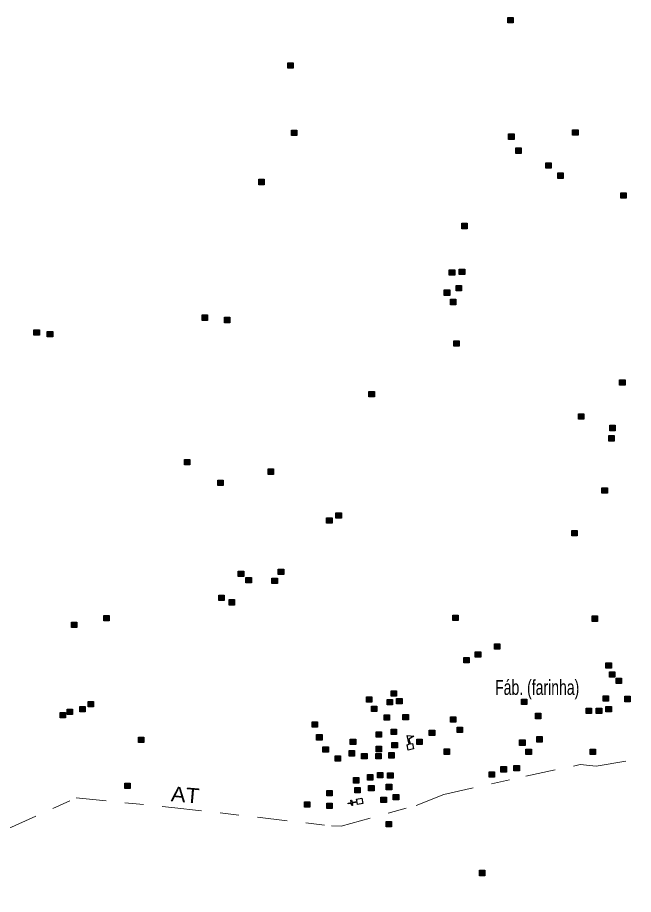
# Model space of a CAD drawing. Extents: x 220.8 to 246.7, y 7287.6 to 7315.8.
# Drawn here: x 236.618 to 239.906, y 7306.501 to 7311.184 of the extents above; entities that cross this region are included whole.
import ezdxf
from ezdxf.enums import TextEntityAlignment as Align

# ---------------------------------------------------------------- set-up
doc = ezdxf.new("R2010")
doc.units = 0
doc.header["$LTSCALE"] = 0.032
doc.linetypes.add('DOT_DASHED', pattern=[7.7, 5, -1.2, 0.3, -1.2])
for name, color, linetype, lineweight in [('2', 7, 'Continuous', 25), ('4', 7, 'Continuous', 25), ('56', 7, 'DOT_DASHED', 13), ('6', 7, 'Continuous', 25)]:
    doc.layers.add(name, color=color, linetype=linetype, lineweight=lineweight)
doc.layers.add('61', color=7, linetype='Continuous')

msp = doc.modelspace()

# ---------------------------------------------------------------- hatches: boundary and pattern name
at = {"layer": '2'}
for points in [[(239.235, 7311.1838), (239.264, 7311.1838), (239.264, 7311.1548), (239.235, 7311.1548)], [(238.0608, 7310.9416), (238.0898, 7310.9416), (238.0898, 7310.9126), (238.0608, 7310.9126)], [(238.0807, 7310.5831), (238.1097, 7310.5831), (238.1097, 7310.5541), (238.0807, 7310.5541)], [(239.2396, 7310.5621), (239.2686, 7310.5621), (239.2686, 7310.5331), (239.2396, 7310.5331)], [(239.5811, 7310.5847), (239.6101, 7310.5847), (239.6101, 7310.5557), (239.5811, 7310.5557)], [(239.278, 7310.4874), (239.307, 7310.4874), (239.307, 7310.4584), (239.278, 7310.4584)], [(239.4386, 7310.4083), (239.4676, 7310.4083), (239.4676, 7310.3793), (239.4386, 7310.3793)], [(237.9055, 7310.3202), (237.9345, 7310.3202), (237.9345, 7310.2912), (237.9055, 7310.2912)], [(239.5019, 7310.354), (239.5309, 7310.354), (239.5309, 7310.325), (239.5019, 7310.325)], [(239.8389, 7310.2477), (239.8679, 7310.2477), (239.8679, 7310.2187), (239.8389, 7310.2187)], [(238.9898, 7310.0849), (239.0188, 7310.0849), (239.0188, 7310.0559), (238.9898, 7310.0559)], [(238.9229, 7309.8363), (238.9519, 7309.8363), (238.9519, 7309.8073), (238.9229, 7309.8073)], [(238.9765, 7309.8397), (239.0055, 7309.8397), (239.0055, 7309.8107), (238.9765, 7309.8107)], [(238.8961, 7309.7292), (238.9251, 7309.7292), (238.9251, 7309.7002), (238.8961, 7309.7002)], [(238.9597, 7309.7526), (238.9887, 7309.7526), (238.9887, 7309.7236), (238.9597, 7309.7236)], [(238.9296, 7309.679), (238.9586, 7309.679), (238.9586, 7309.65), (238.9296, 7309.65)], [(237.6034, 7309.5957), (237.6324, 7309.5957), (237.6324, 7309.5667), (237.6034, 7309.5667)], [(237.7232, 7309.5828), (237.7522, 7309.5828), (237.7522, 7309.5538), (237.7232, 7309.5538)], [(236.7062, 7309.5166), (236.7352, 7309.5166), (236.7352, 7309.4876), (236.7062, 7309.4876)], [(236.777, 7309.5071), (236.806, 7309.5071), (236.806, 7309.4781), (236.777, 7309.4781)], [(238.9464, 7309.458), (238.9754, 7309.458), (238.9754, 7309.429), (238.9464, 7309.429)], [(239.8322, 7309.2493), (239.8612, 7309.2493), (239.8612, 7309.2203), (239.8322, 7309.2203)], [(238.4944, 7309.1868), (238.5234, 7309.1868), (238.5234, 7309.1578), (238.4944, 7309.1578)], [(239.6119, 7309.0679), (239.6409, 7309.0679), (239.6409, 7309.0389), (239.6119, 7309.0389)], [(239.7803, 7309.0063), (239.8093, 7309.0063), (239.8093, 7308.9773), (239.7803, 7308.9773)], [(239.7738, 7308.9512), (239.8028, 7308.9512), (239.8028, 7308.9222), (239.7738, 7308.9222)], [(237.5091, 7308.8237), (237.5381, 7308.8237), (237.5381, 7308.7947), (237.5091, 7308.7947)], [(237.9565, 7308.7731), (237.9855, 7308.7731), (237.9855, 7308.7441), (237.9565, 7308.7441)], [(237.6869, 7308.7132), (237.7159, 7308.7132), (237.7159, 7308.6842), (237.6869, 7308.6842)], [(239.7382, 7308.6726), (239.7672, 7308.6726), (239.7672, 7308.6436), (239.7382, 7308.6436)], [(238.2682, 7308.5123), (238.2972, 7308.5123), (238.2972, 7308.4833), (238.2682, 7308.4833)], [(238.3178, 7308.5385), (238.3468, 7308.5385), (238.3468, 7308.5095), (238.3178, 7308.5095)], [(239.5768, 7308.4445), (239.6058, 7308.4445), (239.6058, 7308.4155), (239.5768, 7308.4155)], [(237.7967, 7308.2279), (237.8257, 7308.2279), (237.8257, 7308.1989), (237.7967, 7308.1989)], [(238.0104, 7308.2381), (238.0394, 7308.2381), (238.0394, 7308.2091), (238.0104, 7308.2091)], [(237.8374, 7308.194), (237.8664, 7308.194), (237.8664, 7308.165), (237.8374, 7308.165)], [(237.9764, 7308.1906), (238.0054, 7308.1906), (238.0054, 7308.1616), (237.9764, 7308.1616)], [(237.6932, 7308.099), (237.7222, 7308.099), (237.7222, 7308.07), (237.6932, 7308.07)], [(237.7475, 7308.0753), (237.7765, 7308.0753), (237.7765, 7308.0463), (237.7475, 7308.0463)], [(237.079, 7307.9907), (237.108, 7307.9907), (237.108, 7307.9617), (237.079, 7307.9617)], [(238.9422, 7307.9929), (238.9712, 7307.9929), (238.9712, 7307.9639), (238.9422, 7307.9639)], [(239.6857, 7307.9878), (239.7147, 7307.9878), (239.7147, 7307.9588), (239.6857, 7307.9588)], [(236.9056, 7307.9554), (236.9346, 7307.9554), (236.9346, 7307.9264), (236.9056, 7307.9264)], [(239.1646, 7307.8396), (239.1936, 7307.8396), (239.1936, 7307.8106), (239.1646, 7307.8106)], [(239.0618, 7307.7968), (239.0908, 7307.7968), (239.0908, 7307.7678), (239.0618, 7307.7678)], [(239.0004, 7307.7661), (239.0294, 7307.7661), (239.0294, 7307.7371), (239.0004, 7307.7371)], [(239.7593, 7307.7378), (239.7883, 7307.7378), (239.7883, 7307.7088), (239.7593, 7307.7088)], [(239.7775, 7307.6893), (239.8065, 7307.6893), (239.8065, 7307.6603), (239.7775, 7307.6603)], [(239.8138, 7307.656), (239.8428, 7307.656), (239.8428, 7307.627), (239.8138, 7307.627)], [(238.4805, 7307.5563), (238.5095, 7307.5563), (238.5095, 7307.5273), (238.4805, 7307.5273)], [(238.6127, 7307.5878), (238.6417, 7307.5878), (238.6417, 7307.5588), (238.6127, 7307.5588)], [(239.7441, 7307.562), (239.7731, 7307.562), (239.7731, 7307.533), (239.7441, 7307.533)], [(239.8593, 7307.559), (239.8883, 7307.559), (239.8883, 7307.53), (239.8593, 7307.53)], [(236.9946, 7307.5313), (237.0236, 7307.5313), (237.0236, 7307.5023), (236.9946, 7307.5023)], [(238.5917, 7307.5416), (238.6207, 7307.5416), (238.6207, 7307.5126), (238.5917, 7307.5126)], [(238.642, 7307.5479), (238.671, 7307.5479), (238.671, 7307.5189), (238.642, 7307.5189)], [(239.3078, 7307.5438), (239.3368, 7307.5438), (239.3368, 7307.5148), (239.3078, 7307.5148)], [(236.8456, 7307.4729), (236.8746, 7307.4729), (236.8746, 7307.4439), (236.8456, 7307.4439)], [(236.8836, 7307.4904), (236.9126, 7307.4904), (236.9126, 7307.4614), (236.8836, 7307.4614)], [(236.9508, 7307.505), (236.9798, 7307.505), (236.9798, 7307.476), (236.9508, 7307.476)], [(238.5077, 7307.506), (238.5367, 7307.506), (238.5367, 7307.477), (238.5077, 7307.477)], [(239.3835, 7307.4681), (239.4125, 7307.4681), (239.4125, 7307.4391), (239.3835, 7307.4391)], [(239.6532, 7307.4954), (239.6822, 7307.4954), (239.6822, 7307.4664), (239.6532, 7307.4664)], [(239.7078, 7307.4954), (239.7368, 7307.4954), (239.7368, 7307.4664), (239.7078, 7307.4664)], [(239.7593, 7307.5045), (239.7883, 7307.5045), (239.7883, 7307.4755), (239.7593, 7307.4755)], [(238.1911, 7307.4223), (238.2201, 7307.4223), (238.2201, 7307.3933), (238.1911, 7307.3933)], [(238.5749, 7307.4598), (238.6039, 7307.4598), (238.6039, 7307.4308), (238.5749, 7307.4308)], [(238.6756, 7307.4619), (238.7046, 7307.4619), (238.7046, 7307.4329), (238.6756, 7307.4329)], [(238.9294, 7307.4492), (238.9584, 7307.4492), (238.9584, 7307.4202), (238.9294, 7307.4202)], [(238.5329, 7307.3696), (238.5619, 7307.3696), (238.5619, 7307.3406), (238.5329, 7307.3406)], [(238.6127, 7307.3843), (238.6417, 7307.3843), (238.6417, 7307.3553), (238.6127, 7307.3553)], [(238.8162, 7307.378), (238.8452, 7307.378), (238.8452, 7307.349), (238.8162, 7307.349)], [(238.9651, 7307.3938), (238.9941, 7307.3938), (238.9941, 7307.3648), (238.9651, 7307.3648)], [(237.2634, 7307.3414), (237.2924, 7307.3414), (237.2924, 7307.3124), (237.2634, 7307.3124)], [(238.2149, 7307.3542), (238.2439, 7307.3542), (238.2439, 7307.3252), (238.2149, 7307.3252)], [(238.3944, 7307.3297), (238.4234, 7307.3297), (238.4234, 7307.3007), (238.3944, 7307.3007)], [(238.7491, 7307.3297), (238.7781, 7307.3297), (238.7781, 7307.3007), (238.7491, 7307.3007)], [(239.2987, 7307.3257), (239.3277, 7307.3257), (239.3277, 7307.2967), (239.2987, 7307.2967)], [(239.3896, 7307.3439), (239.4186, 7307.3439), (239.4186, 7307.3149), (239.3896, 7307.3149)], [(238.2489, 7307.2896), (238.2779, 7307.2896), (238.2779, 7307.2606), (238.2489, 7307.2606)], [(238.5329, 7307.2919), (238.5619, 7307.2919), (238.5619, 7307.2629), (238.5329, 7307.2629)], [(238.6169, 7307.3129), (238.6459, 7307.3129), (238.6459, 7307.2839), (238.6169, 7307.2839)], [(238.8949, 7307.278), (238.9239, 7307.278), (238.9239, 7307.249), (238.8949, 7307.249)], [(239.332, 7307.2772), (239.361, 7307.2772), (239.361, 7307.2482), (239.332, 7307.2482)], [(239.6744, 7307.2772), (239.7034, 7307.2772), (239.7034, 7307.2482), (239.6744, 7307.2482)], [(238.3136, 7307.2419), (238.3426, 7307.2419), (238.3426, 7307.2129), (238.3136, 7307.2129)], [(238.3881, 7307.2689), (238.4171, 7307.2689), (238.4171, 7307.2399), (238.3881, 7307.2399)], [(238.4553, 7307.2542), (238.4843, 7307.2542), (238.4843, 7307.2252), (238.4553, 7307.2252)], [(238.5308, 7307.2542), (238.5598, 7307.2542), (238.5598, 7307.2252), (238.5308, 7307.2252)], [(238.6001, 7307.2584), (238.6291, 7307.2584), (238.6291, 7307.2294), (238.6001, 7307.2294)], [(239.1987, 7307.1833), (239.2277, 7307.1833), (239.2277, 7307.1543), (239.1987, 7307.1543)], [(239.2684, 7307.1893), (239.2974, 7307.1893), (239.2974, 7307.1603), (239.2684, 7307.1603)], [(238.4867, 7307.1405), (238.5157, 7307.1405), (238.5157, 7307.1115), (238.4867, 7307.1115)], [(238.5395, 7307.1519), (238.5685, 7307.1519), (238.5685, 7307.1229), (238.5395, 7307.1229)], [(238.5939, 7307.1505), (238.6229, 7307.1505), (238.6229, 7307.1215), (238.5939, 7307.1215)], [(239.1351, 7307.156), (239.1641, 7307.156), (239.1641, 7307.127), (239.1351, 7307.127)], [(237.1904, 7307.0959), (237.2194, 7307.0959), (237.2194, 7307.0669), (237.1904, 7307.0669)], [(238.4109, 7307.1248), (238.4399, 7307.1248), (238.4399, 7307.0958), (238.4109, 7307.0958)], [(238.5867, 7307.089), (238.6157, 7307.089), (238.6157, 7307.06), (238.5867, 7307.06)], [(238.2697, 7307.0559), (238.2987, 7307.0559), (238.2987, 7307.0269), (238.2697, 7307.0269)], [(238.418, 7307.0719), (238.447, 7307.0719), (238.447, 7307.0429), (238.418, 7307.0429)], [(238.4924, 7307.0833), (238.5214, 7307.0833), (238.5214, 7307.0543), (238.4924, 7307.0543)], [(238.1496, 7306.9953), (238.1786, 7306.9953), (238.1786, 7306.9663), (238.1496, 7306.9663)], [(238.5581, 7307.0204), (238.5871, 7307.0204), (238.5871, 7306.9914), (238.5581, 7306.9914)], [(238.6239, 7307.0347), (238.6529, 7307.0347), (238.6529, 7307.0057), (238.6239, 7307.0057)], [(238.2687, 7306.9882), (238.2977, 7306.9882), (238.2977, 7306.9592), (238.2687, 7306.9592)], [(238.5858, 7306.8901), (238.6148, 7306.8901), (238.6148, 7306.8611), (238.5858, 7306.8611)], [(239.0838, 7306.6298), (239.1128, 7306.6298), (239.1128, 7306.6008), (239.0838, 7306.6008)]]:
    msp.add_hatch(color=256, dxfattribs=at).paths.add_polyline_path(points)

# ---------------------------------------------------------------- linework, layer by layer
for points in [[(239.235, 7311.1838), (239.264, 7311.1838), (239.264, 7311.1548), (239.235, 7311.1548)], [(238.0608, 7310.9416), (238.0898, 7310.9416), (238.0898, 7310.9126), (238.0608, 7310.9126)], [(238.0807, 7310.5831), (238.1097, 7310.5831), (238.1097, 7310.5541), (238.0807, 7310.5541)], [(239.2396, 7310.5621), (239.2686, 7310.5621), (239.2686, 7310.5331), (239.2396, 7310.5331)], [(239.5811, 7310.5847), (239.6101, 7310.5847), (239.6101, 7310.5557), (239.5811, 7310.5557)], [(239.278, 7310.4874), (239.307, 7310.4874), (239.307, 7310.4584), (239.278, 7310.4584)], [(239.4386, 7310.4083), (239.4676, 7310.4083), (239.4676, 7310.3793), (239.4386, 7310.3793)], [(237.9055, 7310.3202), (237.9345, 7310.3202), (237.9345, 7310.2912), (237.9055, 7310.2912)], [(239.5019, 7310.354), (239.5309, 7310.354), (239.5309, 7310.325), (239.5019, 7310.325)], [(239.8389, 7310.2477), (239.8679, 7310.2477), (239.8679, 7310.2187), (239.8389, 7310.2187)], [(238.9898, 7310.0849), (239.0188, 7310.0849), (239.0188, 7310.0559), (238.9898, 7310.0559)], [(238.9229, 7309.8363), (238.9519, 7309.8363), (238.9519, 7309.8073), (238.9229, 7309.8073)], [(238.9765, 7309.8397), (239.0055, 7309.8397), (239.0055, 7309.8107), (238.9765, 7309.8107)], [(238.8961, 7309.7292), (238.9251, 7309.7292), (238.9251, 7309.7002), (238.8961, 7309.7002)], [(238.9597, 7309.7526), (238.9887, 7309.7526), (238.9887, 7309.7236), (238.9597, 7309.7236)], [(238.9296, 7309.679), (238.9586, 7309.679), (238.9586, 7309.65), (238.9296, 7309.65)], [(237.6034, 7309.5957), (237.6324, 7309.5957), (237.6324, 7309.5667), (237.6034, 7309.5667)], [(237.7232, 7309.5828), (237.7522, 7309.5828), (237.7522, 7309.5538), (237.7232, 7309.5538)], [(236.7062, 7309.5166), (236.7352, 7309.5166), (236.7352, 7309.4876), (236.7062, 7309.4876)], [(236.777, 7309.5071), (236.806, 7309.5071), (236.806, 7309.4781), (236.777, 7309.4781)], [(238.9464, 7309.458), (238.9754, 7309.458), (238.9754, 7309.429), (238.9464, 7309.429)], [(239.8322, 7309.2493), (239.8612, 7309.2493), (239.8612, 7309.2203), (239.8322, 7309.2203)], [(238.4944, 7309.1868), (238.5234, 7309.1868), (238.5234, 7309.1578), (238.4944, 7309.1578)], [(239.6119, 7309.0679), (239.6409, 7309.0679), (239.6409, 7309.0389), (239.6119, 7309.0389)], [(239.7803, 7309.0063), (239.8093, 7309.0063), (239.8093, 7308.9773), (239.7803, 7308.9773)], [(239.7738, 7308.9512), (239.8028, 7308.9512), (239.8028, 7308.9222), (239.7738, 7308.9222)], [(237.5091, 7308.8237), (237.5381, 7308.8237), (237.5381, 7308.7947), (237.5091, 7308.7947)], [(237.9565, 7308.7731), (237.9855, 7308.7731), (237.9855, 7308.7441), (237.9565, 7308.7441)], [(237.6869, 7308.7132), (237.7159, 7308.7132), (237.7159, 7308.6842), (237.6869, 7308.6842)], [(239.7382, 7308.6726), (239.7672, 7308.6726), (239.7672, 7308.6436), (239.7382, 7308.6436)], [(238.2682, 7308.5123), (238.2972, 7308.5123), (238.2972, 7308.4833), (238.2682, 7308.4833)], [(238.3178, 7308.5385), (238.3468, 7308.5385), (238.3468, 7308.5095), (238.3178, 7308.5095)], [(239.5768, 7308.4445), (239.6058, 7308.4445), (239.6058, 7308.4155), (239.5768, 7308.4155)], [(237.7967, 7308.2279), (237.8257, 7308.2279), (237.8257, 7308.1989), (237.7967, 7308.1989)], [(238.0104, 7308.2381), (238.0394, 7308.2381), (238.0394, 7308.2091), (238.0104, 7308.2091)], [(237.8374, 7308.194), (237.8664, 7308.194), (237.8664, 7308.165), (237.8374, 7308.165)], [(237.9764, 7308.1906), (238.0054, 7308.1906), (238.0054, 7308.1616), (237.9764, 7308.1616)], [(237.6932, 7308.099), (237.7222, 7308.099), (237.7222, 7308.07), (237.6932, 7308.07)], [(237.7475, 7308.0753), (237.7765, 7308.0753), (237.7765, 7308.0463), (237.7475, 7308.0463)], [(237.079, 7307.9907), (237.108, 7307.9907), (237.108, 7307.9617), (237.079, 7307.9617)], [(238.9422, 7307.9929), (238.9712, 7307.9929), (238.9712, 7307.9639), (238.9422, 7307.9639)], [(239.6857, 7307.9878), (239.7147, 7307.9878), (239.7147, 7307.9588), (239.6857, 7307.9588)], [(236.9056, 7307.9554), (236.9346, 7307.9554), (236.9346, 7307.9264), (236.9056, 7307.9264)], [(239.1646, 7307.8396), (239.1936, 7307.8396), (239.1936, 7307.8106), (239.1646, 7307.8106)], [(239.0618, 7307.7968), (239.0908, 7307.7968), (239.0908, 7307.7678), (239.0618, 7307.7678)], [(239.0004, 7307.7661), (239.0294, 7307.7661), (239.0294, 7307.7371), (239.0004, 7307.7371)], [(239.7593, 7307.7378), (239.7883, 7307.7378), (239.7883, 7307.7088), (239.7593, 7307.7088)], [(239.7775, 7307.6893), (239.8065, 7307.6893), (239.8065, 7307.6603), (239.7775, 7307.6603)], [(239.8138, 7307.656), (239.8428, 7307.656), (239.8428, 7307.627), (239.8138, 7307.627)], [(238.4805, 7307.5563), (238.5095, 7307.5563), (238.5095, 7307.5273), (238.4805, 7307.5273)], [(238.6127, 7307.5878), (238.6417, 7307.5878), (238.6417, 7307.5588), (238.6127, 7307.5588)], [(239.7441, 7307.562), (239.7731, 7307.562), (239.7731, 7307.533), (239.7441, 7307.533)], [(239.8593, 7307.559), (239.8883, 7307.559), (239.8883, 7307.53), (239.8593, 7307.53)], [(236.9946, 7307.5313), (237.0236, 7307.5313), (237.0236, 7307.5023), (236.9946, 7307.5023)], [(238.5917, 7307.5416), (238.6207, 7307.5416), (238.6207, 7307.5126), (238.5917, 7307.5126)], [(238.642, 7307.5479), (238.671, 7307.5479), (238.671, 7307.5189), (238.642, 7307.5189)], [(239.3078, 7307.5438), (239.3368, 7307.5438), (239.3368, 7307.5148), (239.3078, 7307.5148)], [(236.8456, 7307.4729), (236.8746, 7307.4729), (236.8746, 7307.4439), (236.8456, 7307.4439)], [(236.8836, 7307.4904), (236.9126, 7307.4904), (236.9126, 7307.4614), (236.8836, 7307.4614)], [(236.9508, 7307.505), (236.9798, 7307.505), (236.9798, 7307.476), (236.9508, 7307.476)], [(238.5077, 7307.506), (238.5367, 7307.506), (238.5367, 7307.477), (238.5077, 7307.477)], [(239.3835, 7307.4681), (239.4125, 7307.4681), (239.4125, 7307.4391), (239.3835, 7307.4391)], [(239.6532, 7307.4954), (239.6822, 7307.4954), (239.6822, 7307.4664), (239.6532, 7307.4664)], [(239.7078, 7307.4954), (239.7368, 7307.4954), (239.7368, 7307.4664), (239.7078, 7307.4664)], [(239.7593, 7307.5045), (239.7883, 7307.5045), (239.7883, 7307.4755), (239.7593, 7307.4755)], [(238.1911, 7307.4223), (238.2201, 7307.4223), (238.2201, 7307.3933), (238.1911, 7307.3933)], [(238.5749, 7307.4598), (238.6039, 7307.4598), (238.6039, 7307.4308), (238.5749, 7307.4308)], [(238.6756, 7307.4619), (238.7046, 7307.4619), (238.7046, 7307.4329), (238.6756, 7307.4329)], [(238.9294, 7307.4492), (238.9584, 7307.4492), (238.9584, 7307.4202), (238.9294, 7307.4202)], [(238.5329, 7307.3696), (238.5619, 7307.3696), (238.5619, 7307.3406), (238.5329, 7307.3406)], [(238.6127, 7307.3843), (238.6417, 7307.3843), (238.6417, 7307.3553), (238.6127, 7307.3553)], [(238.8162, 7307.378), (238.8452, 7307.378), (238.8452, 7307.349), (238.8162, 7307.349)], [(238.9651, 7307.3938), (238.9941, 7307.3938), (238.9941, 7307.3648), (238.9651, 7307.3648)], [(237.2634, 7307.3414), (237.2924, 7307.3414), (237.2924, 7307.3124), (237.2634, 7307.3124)], [(238.2149, 7307.3542), (238.2439, 7307.3542), (238.2439, 7307.3252), (238.2149, 7307.3252)], [(238.3944, 7307.3297), (238.4234, 7307.3297), (238.4234, 7307.3007), (238.3944, 7307.3007)], [(238.7491, 7307.3297), (238.7781, 7307.3297), (238.7781, 7307.3007), (238.7491, 7307.3007)], [(239.2987, 7307.3257), (239.3277, 7307.3257), (239.3277, 7307.2967), (239.2987, 7307.2967)], [(239.3896, 7307.3439), (239.4186, 7307.3439), (239.4186, 7307.3149), (239.3896, 7307.3149)], [(238.2489, 7307.2896), (238.2779, 7307.2896), (238.2779, 7307.2606), (238.2489, 7307.2606)], [(238.5329, 7307.2919), (238.5619, 7307.2919), (238.5619, 7307.2629), (238.5329, 7307.2629)], [(238.6169, 7307.3129), (238.6459, 7307.3129), (238.6459, 7307.2839), (238.6169, 7307.2839)], [(238.8949, 7307.278), (238.9239, 7307.278), (238.9239, 7307.249), (238.8949, 7307.249)], [(239.332, 7307.2772), (239.361, 7307.2772), (239.361, 7307.2482), (239.332, 7307.2482)], [(239.6744, 7307.2772), (239.7034, 7307.2772), (239.7034, 7307.2482), (239.6744, 7307.2482)], [(238.3136, 7307.2419), (238.3426, 7307.2419), (238.3426, 7307.2129), (238.3136, 7307.2129)], [(238.3881, 7307.2689), (238.4171, 7307.2689), (238.4171, 7307.2399), (238.3881, 7307.2399)], [(238.4553, 7307.2542), (238.4843, 7307.2542), (238.4843, 7307.2252), (238.4553, 7307.2252)], [(238.5308, 7307.2542), (238.5598, 7307.2542), (238.5598, 7307.2252), (238.5308, 7307.2252)], [(238.6001, 7307.2584), (238.6291, 7307.2584), (238.6291, 7307.2294), (238.6001, 7307.2294)], [(239.1987, 7307.1833), (239.2277, 7307.1833), (239.2277, 7307.1543), (239.1987, 7307.1543)], [(239.2684, 7307.1893), (239.2974, 7307.1893), (239.2974, 7307.1603), (239.2684, 7307.1603)], [(238.4867, 7307.1405), (238.5157, 7307.1405), (238.5157, 7307.1115), (238.4867, 7307.1115)], [(238.5395, 7307.1519), (238.5685, 7307.1519), (238.5685, 7307.1229), (238.5395, 7307.1229)], [(238.5939, 7307.1505), (238.6229, 7307.1505), (238.6229, 7307.1215), (238.5939, 7307.1215)], [(239.1351, 7307.156), (239.1641, 7307.156), (239.1641, 7307.127), (239.1351, 7307.127)], [(237.1904, 7307.0959), (237.2194, 7307.0959), (237.2194, 7307.0669), (237.1904, 7307.0669)], [(238.4109, 7307.1248), (238.4399, 7307.1248), (238.4399, 7307.0958), (238.4109, 7307.0958)], [(238.5867, 7307.089), (238.6157, 7307.089), (238.6157, 7307.06), (238.5867, 7307.06)], [(238.2697, 7307.0559), (238.2987, 7307.0559), (238.2987, 7307.0269), (238.2697, 7307.0269)], [(238.418, 7307.0719), (238.447, 7307.0719), (238.447, 7307.0429), (238.418, 7307.0429)], [(238.4924, 7307.0833), (238.5214, 7307.0833), (238.5214, 7307.0543), (238.4924, 7307.0543)], [(238.1496, 7306.9953), (238.1786, 7306.9953), (238.1786, 7306.9663), (238.1496, 7306.9663)], [(238.5581, 7307.0204), (238.5871, 7307.0204), (238.5871, 7306.9914), (238.5581, 7306.9914)], [(238.6239, 7307.0347), (238.6529, 7307.0347), (238.6529, 7307.0057), (238.6239, 7307.0057)], [(238.2687, 7306.9882), (238.2977, 7306.9882), (238.2977, 7306.9592), (238.2687, 7306.9592)], [(238.5858, 7306.8901), (238.6148, 7306.8901), (238.6148, 7306.8611), (238.5858, 7306.8611)], [(239.0838, 7306.6298), (239.1128, 7306.6298), (239.1128, 7306.6008), (239.0838, 7306.6008)]]:
    msp.add_lwpolyline(points, close=True, dxfattribs=at)
at = {"layer": '4'}
for points in [[(238.7092, 7307.3031), (238.698, 7307.3502), (238.7336, 7307.3468), (238.7079, 7307.3296), (238.714, 7307.3043)], [(238.714, 7307.3043), (238.7258, 7307.3071), (238.7325, 7307.2789), (238.7043, 7307.2721), (238.6976, 7307.3003), (238.7092, 7307.3031)]]:
    msp.add_lwpolyline(points, dxfattribs=at)
at = {"layer": '56'}
msp.add_lwpolyline([(233.3657, 7306.6808), (233.9802, 7306.8124), (234.0015, 7306.8162), (234.1355, 7306.8375), (234.184, 7306.8362), (234.3746, 7306.8002), (234.4423, 7306.7876), (235.2612, 7306.6381), (235.7845, 7306.5007), (236.1507, 7306.6634), (236.9321, 7307.0166), (237.442, 7306.9659), (238.2941, 7306.8672), (238.3461, 7306.8646), (238.7464, 7306.9763), (238.8939, 7307.0343), (239.3316, 7307.1323), (239.6224, 7307.1942), (239.7076, 7307.1857), (239.9155, 7307.2208)], dxfattribs=at)
at = {"layer": '6'}
for points in [[(238.4315, 7306.9933), (238.4049, 7306.9882), (238.4072, 7306.9763), (238.4023, 7306.9754), (238.4001, 7306.9873), (238.384, 7306.9842), (238.383, 7306.9889), (238.3992, 7306.992), (238.3969, 7307.0039), (238.4017, 7307.0048), (238.404, 7306.9929), (238.4306, 7306.998)], [(238.4306, 7306.998), (238.4283, 7307.0099), (238.4568, 7307.0154), (238.4622, 7306.9869), (238.4338, 7306.9814), (238.4315, 7306.9933)]]:
    msp.add_lwpolyline(points, dxfattribs=at)

# ---------------------------------------------------------------- texts
at = {"layer": '61', "width": 0.7}
msp.add_text('Fáb. (farinha)', height=0.08, dxfattribs=at).set_placement((239.1675, 7307.5666))
at = {"layer": '61', "width": 1.1}
msp.add_text('AT', height=0.08, rotation=355.092, dxfattribs=at).set_placement((237.5097, 7306.9927), align=Align.CENTER)

doc.saveas('drawing.dxf')
